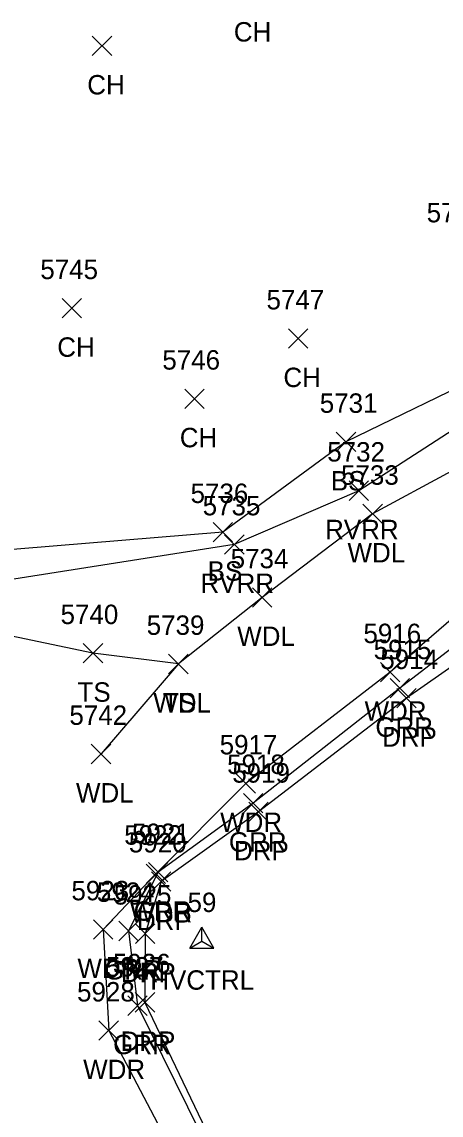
# Model space of a CAD drawing. Extents: x 1618146 to 1620418, y 640749 to 641927.
# Drawn here: x 1619954.7 to 1619997.9, y 641136.7 to 641249.3 of the extents above; entities that cross this region are included whole.
import ezdxf

# ---------------------------------------------------------------- set-up
doc = ezdxf.new("R2010")
doc.units = 0
for name, color, linetype in [('C_A', 7, 'Continuous'), ('C_I', 7, 'Continuous'), ('CPSM', 7, 'Continuous'), ('L_A', 7, 'Continuous'), ('L_I', 7, 'Continuous'), ('L_TIC', 7, 'Continuous'), ('LAWA', 7, 'Continuous'), ('LAWE', 7, 'Continuous'), ('LELB', 7, 'Continuous'), ('R_A', 7, 'Continuous'), ('R_I', 7, 'Continuous'), ('R_TIC', 7, 'Continuous'), ('RDP', 7, 'Continuous'), ('RGR', 7, 'Continuous')]:
    doc.layers.add(name, color=color, linetype=linetype)

msp = doc.modelspace()

# ---------------------------------------------------------------- linework, layer by layer
at = {"layer": 'CPSM'}
for p, q in [((1619972.01, 641153.92), (1619973.26, 641156.09)), ((1619974.51, 641153.92), (1619973.26, 641156.09)), ((1619973.26, 641154.64), (1619973.26, 641156.09)), ((1619972.01, 641153.92), (1619973.26, 641154.64)), ((1619973.26, 641154.64), (1619973.26, 641154.64)), ((1619973.26, 641154.64), (1619974.51, 641153.92)), ((1619972.01, 641153.92), (1619974.51, 641153.92))]:
    msp.add_line(p, q, dxfattribs=at)
at = {"layer": 'L_TIC'}
for points in [[(1619961.97, 641245.85), (1619963.97, 641247.85)], [(1619963.97, 641245.85), (1619961.97, 641247.85)], [(1619958.87, 641218.83), (1619960.87, 641220.83)], [(1619960.87, 641218.83), (1619958.87, 641220.83)], [(1619982.18, 641215.71), (1619984.18, 641217.71)], [(1619984.18, 641215.71), (1619982.18, 641217.71)], [(1619971.51, 641209.51), (1619973.51, 641211.51)], [(1619973.51, 641209.51), (1619971.51, 641211.51)], [(1619987.12, 641205.06), (1619989.12, 641207.06)], [(1619989.12, 641205.06), (1619987.12, 641207.06)], [(1619988.45, 641200.04), (1619990.45, 641202.04)], [(1619990.45, 641200.04), (1619988.45, 641202.04)], [(1619989.87, 641197.65), (1619991.87, 641199.65)], [(1619991.87, 641197.65), (1619989.87, 641199.65)], [(1619974.42, 641195.77), (1619976.42, 641197.77)], [(1619976.42, 641195.77), (1619974.42, 641197.77)], [(1619975.61, 641194.5), (1619977.61, 641196.5)], [(1619977.61, 641194.5), (1619975.61, 641196.5)], [(1619978.49, 641189.05), (1619980.49, 641191.05)], [(1619980.49, 641189.05), (1619978.49, 641191.05)], [(1619961.04, 641183.3), (1619963.04, 641185.3)], [(1619963.04, 641183.3), (1619961.04, 641185.3)], [(1619969.84, 641182.19), (1619971.84, 641184.19)], [(1619971.84, 641182.19), (1619969.84, 641184.19)], [(1619969.84, 641182.19), (1619971.84, 641184.19)], [(1619971.84, 641182.19), (1619969.84, 641184.19)], [(1619991.67, 641181.34), (1619993.67, 641183.34)], [(1619993.67, 641181.34), (1619991.67, 641183.34)], [(1619961.87, 641172.92), (1619963.87, 641174.92)], [(1619963.87, 641172.92), (1619961.87, 641174.92)], [(1619976.79, 641169.88), (1619978.79, 641171.88)], [(1619978.79, 641169.88), (1619976.79, 641171.88)], [(1619967.52, 641160.58), (1619969.52, 641162.58)], [(1619969.52, 641160.58), (1619967.52, 641162.58)], [(1619962.08, 641154.85), (1619964.08, 641156.85)], [(1619964.08, 641154.85), (1619962.08, 641156.85)], [(1619962.66, 641144.43), (1619964.66, 641146.43)], [(1619964.66, 641144.43), (1619962.66, 641146.43)]]:
    msp.add_lwpolyline(points, dxfattribs=at)
at = {"layer": 'LAWA'}
for points in [[(1620016.06, 641211.09), (1620007.14, 641207.45), (1619990.87, 641198.65), (1619979.49, 641190.05), (1619970.84, 641183.19), (1619962.87, 641173.92)], [(1620011.76, 641198.79), (1619992.67, 641182.34), (1619977.79, 641170.88), (1619968.52, 641161.58), (1619963.08, 641155.85), (1619963.66, 641145.43), (1619975.53, 641122.9)]]:
    msp.add_lwpolyline(points, dxfattribs=at)
at = {"layer": 'LAWE'}
msp.add_lwpolyline([(1620126.92, 641247.39), (1620111.12, 641239.46), (1620109.41, 641236.16), (1620101.64, 641234.76), (1620084.09, 641235.91), (1620071.67, 641229.78), (1620042.74, 641224.39), (1620037.79, 641222.07), (1620025.57, 641215.03), (1620021.3, 641209.77), (1620016.06, 641211.09), (1620004.82, 641210.96), (1619989.45, 641201.04), (1619976.61, 641195.5), (1619948.38, 641191.06)], dxfattribs=at)
at = {"layer": 'LELB'}
for points in [[(1620126.92, 641247.39), (1620111.61, 641247.66), (1620106.4, 641242.54), (1620098.53, 641237.32), (1620084.83, 641239.22), (1620069.1, 641232.99), (1620064.28, 641237.2), (1620039.17, 641227.39), (1620035.44, 641222.86), (1620023.48, 641219.07), (1620012.16, 641216.97), (1620003.41, 641213.47), (1619988.12, 641206.06), (1619975.42, 641196.77), (1619947.5, 641194.47)], [(1619970.84, 641183.19), (1619962.04, 641184.3), (1619949.37, 641186.96)]]:
    msp.add_lwpolyline(points, dxfattribs=at)
at = {"layer": 'R_TIC'}
for points in [[(1619992.66, 641179.69), (1619994.66, 641181.69)], [(1619994.66, 641179.69), (1619992.66, 641181.69)], [(1619993.36, 641178.67), (1619995.36, 641180.67)], [(1619995.36, 641178.67), (1619993.36, 641180.67)], [(1619977.56, 641167.86), (1619979.56, 641169.86)], [(1619979.56, 641167.86), (1619977.56, 641169.86)], [(1619978.1, 641166.97), (1619980.1, 641168.97)], [(1619980.1, 641166.97), (1619978.1, 641168.97)], [(1619967.76, 641160.75), (1619969.76, 641162.75)], [(1619969.76, 641160.75), (1619967.76, 641162.75)], [(1619968.08, 641159.78), (1619970.08, 641161.78)], [(1619970.08, 641159.78), (1619968.08, 641161.78)], [(1619964.7, 641154.69), (1619966.7, 641156.69)], [(1619966.7, 641154.69), (1619964.7, 641156.69)], [(1619966.43, 641154.41), (1619968.43, 641156.41)], [(1619968.43, 641154.41), (1619966.43, 641156.41)], [(1619965.63, 641147), (1619967.63, 641149)], [(1619967.63, 641147), (1619965.63, 641149)], [(1619966.4, 641147.34), (1619968.4, 641149.34)], [(1619968.4, 641147.34), (1619966.4, 641149.34)]]:
    msp.add_lwpolyline(points, dxfattribs=at)
at = {"layer": 'RDP'}
msp.add_lwpolyline([(1620043.03, 641194.19), (1620044.89, 641206.84), (1620037.07, 641211.43), (1620013.61, 641193.09), (1619994.36, 641179.67), (1619979.1, 641167.97), (1619969.08, 641160.78), (1619967.43, 641155.41), (1619967.4, 641148.34), (1619978.8, 641124.54), (1619983.9, 641114.17)], dxfattribs=at)
at = {"layer": 'RGR'}
msp.add_lwpolyline([(1620036.71, 641213.17), (1620026.73, 641206.23), (1620011.86, 641194.68), (1619993.66, 641180.69), (1619978.56, 641168.86), (1619968.76, 641161.75), (1619965.7, 641155.69), (1619966.63, 641148), (1619978.24, 641124.49), (1619983.31, 641114)], dxfattribs=at)

# ---------------------------------------------------------------- texts
at = {"layer": 'C_A'}
msp.add_text('HVCTRL', height=2, dxfattribs=at).set_placement((1619967.95, 641149.64))
at = {"layer": 'C_I'}
msp.add_text('59', height=2, dxfattribs=at).set_placement((1619971.79, 641157.64))
at = {"layer": 'L_A'}
for s, p in [('CH', (1619976.56, 641247.3)), ('CH', (1619961.45, 641241.85)), ('CH', (1619958.36, 641214.83)), ('CH', (1619981.67, 641211.71)), ('CH', (1619970.99, 641205.51)), ('BS', (1619986.56, 641201.06)), ('RVRR', (1619985.97, 641196.04)), ('WDL', (1619988.28, 641193.65)), ('BS', (1619973.86, 641191.77)), ('RVRR', (1619973.13, 641190.5)), ('WDL', (1619976.91, 641185.05)), ('TS', (1619960.45, 641179.3)), ('WDL', (1619968.26, 641178.19)), ('TS', (1619969.25, 641178.19)), ('WDR', (1619990.04, 641177.34)), ('WDL', (1619960.29, 641168.92)), ('WDR', (1619975.15, 641165.88)), ('WDR', (1619965.88, 641156.58)), ('WDR', (1619960.44, 641150.85)), ('WDR', (1619961.03, 641140.43))]:
    msp.add_text(s, height=2, dxfattribs=at).set_placement(p)
at = {"layer": 'L_I'}
for s, p in [('5748', (1619996.44, 641228.68)), ('5745', (1619956.61, 641222.83)), ('5747', (1619979.93, 641219.71)), ('5746', (1619969.19, 641213.51)), ('5731', (1619985.42, 641209.06)), ('5732', (1619986.19, 641204.04)), ('5733', (1619987.61, 641201.65)), ('5736', (1619972.1, 641199.77)), ('5735', (1619973.35, 641198.5)), ('5734', (1619976.23, 641193.05)), ('5740', (1619958.7, 641187.3)), ('5739', (1619967.58, 641186.19)), ('5739', (1619967.58, 641186.19)), ('5916', (1619989.92, 641185.34)), ('5742', (1619959.61, 641176.92)), ('5917', (1619975.1, 641173.88)), ('5922', (1619965.26, 641164.58)), ('5923', (1619959.82, 641158.85)), ('5928', (1619960.4, 641148.43))]:
    msp.add_text(s, height=2, dxfattribs=at).set_placement(p)
at = {"layer": 'R_A'}
for s, p in [('GRR', (1619991.15, 641175.69)), ('DRP', (1619991.84, 641174.67)), ('GRR', (1619976.05, 641163.86)), ('DRP', (1619976.58, 641162.97)), ('GRR', (1619966.24, 641156.75)), ('DRP', (1619966.57, 641155.78)), ('GRR', (1619963.19, 641150.69)), ('DRP', (1619964.92, 641150.41)), ('DRP', (1619964.89, 641143.34)), ('GRR', (1619964.12, 641143))]:
    msp.add_text(s, height=2, dxfattribs=at).set_placement(p)
at = {"layer": 'R_I'}
for s, p in [('5915', (1619990.97, 641183.69)), ('5914', (1619991.66, 641182.67)), ('5918', (1619975.87, 641171.86)), ('5919', (1619976.4, 641170.97)), ('5921', (1619966.06, 641164.75)), ('5920', (1619965.74, 641163.78)), ('5924', (1619962.44, 641158.69)), ('5925', (1619964.17, 641158.41)), ('5926', (1619964.09, 641151.34)), ('5927', (1619963.37, 641151))]:
    msp.add_text(s, height=2, dxfattribs=at).set_placement(p)

doc.saveas('drawing.dxf')
